// Mitsubishi GX Works2 project: MC-30MR-4MTS-F700-FX-8C   PLC: FX1S

PROGRAM MAIN
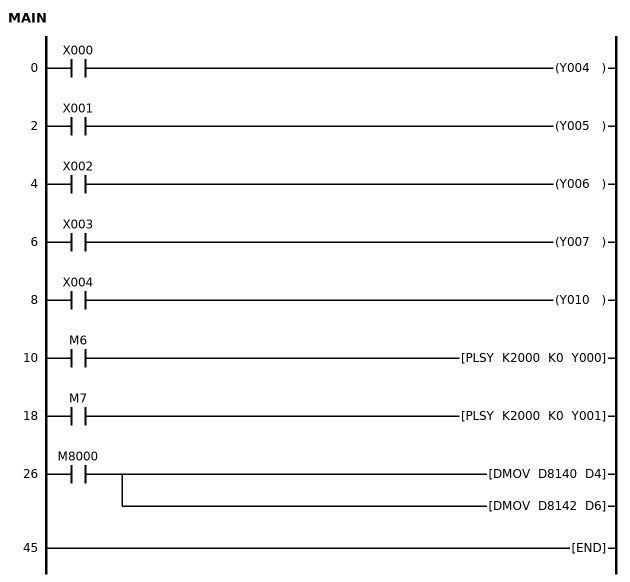
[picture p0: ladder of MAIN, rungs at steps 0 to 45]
0     LD      X000
      OUT     Y004
2     LD      X001
      OUT     Y005
4     LD      X002
      OUT     Y006
6     LD      X003
      OUT     Y007
8     LD      X004
      OUT     Y010
10    LD      M6
      PLSY    K2000 K0 Y000
18    LD      M7
      PLSY    K2000 K0 Y001
26    LD      M8000
      DMOV    D8140 D4
      DMOV    D8142 D6
45    END
END_PROGRAM
